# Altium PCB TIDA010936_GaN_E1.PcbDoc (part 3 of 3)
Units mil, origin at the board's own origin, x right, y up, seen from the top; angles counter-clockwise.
Board outline 2755.91 x 2708.83 mil, 4 copper layers (Top Layer, POWER, GND, Bottom Layer), stack 64.224 mil thick; 223 components, 99 nets, 571 pads, 439 vias.
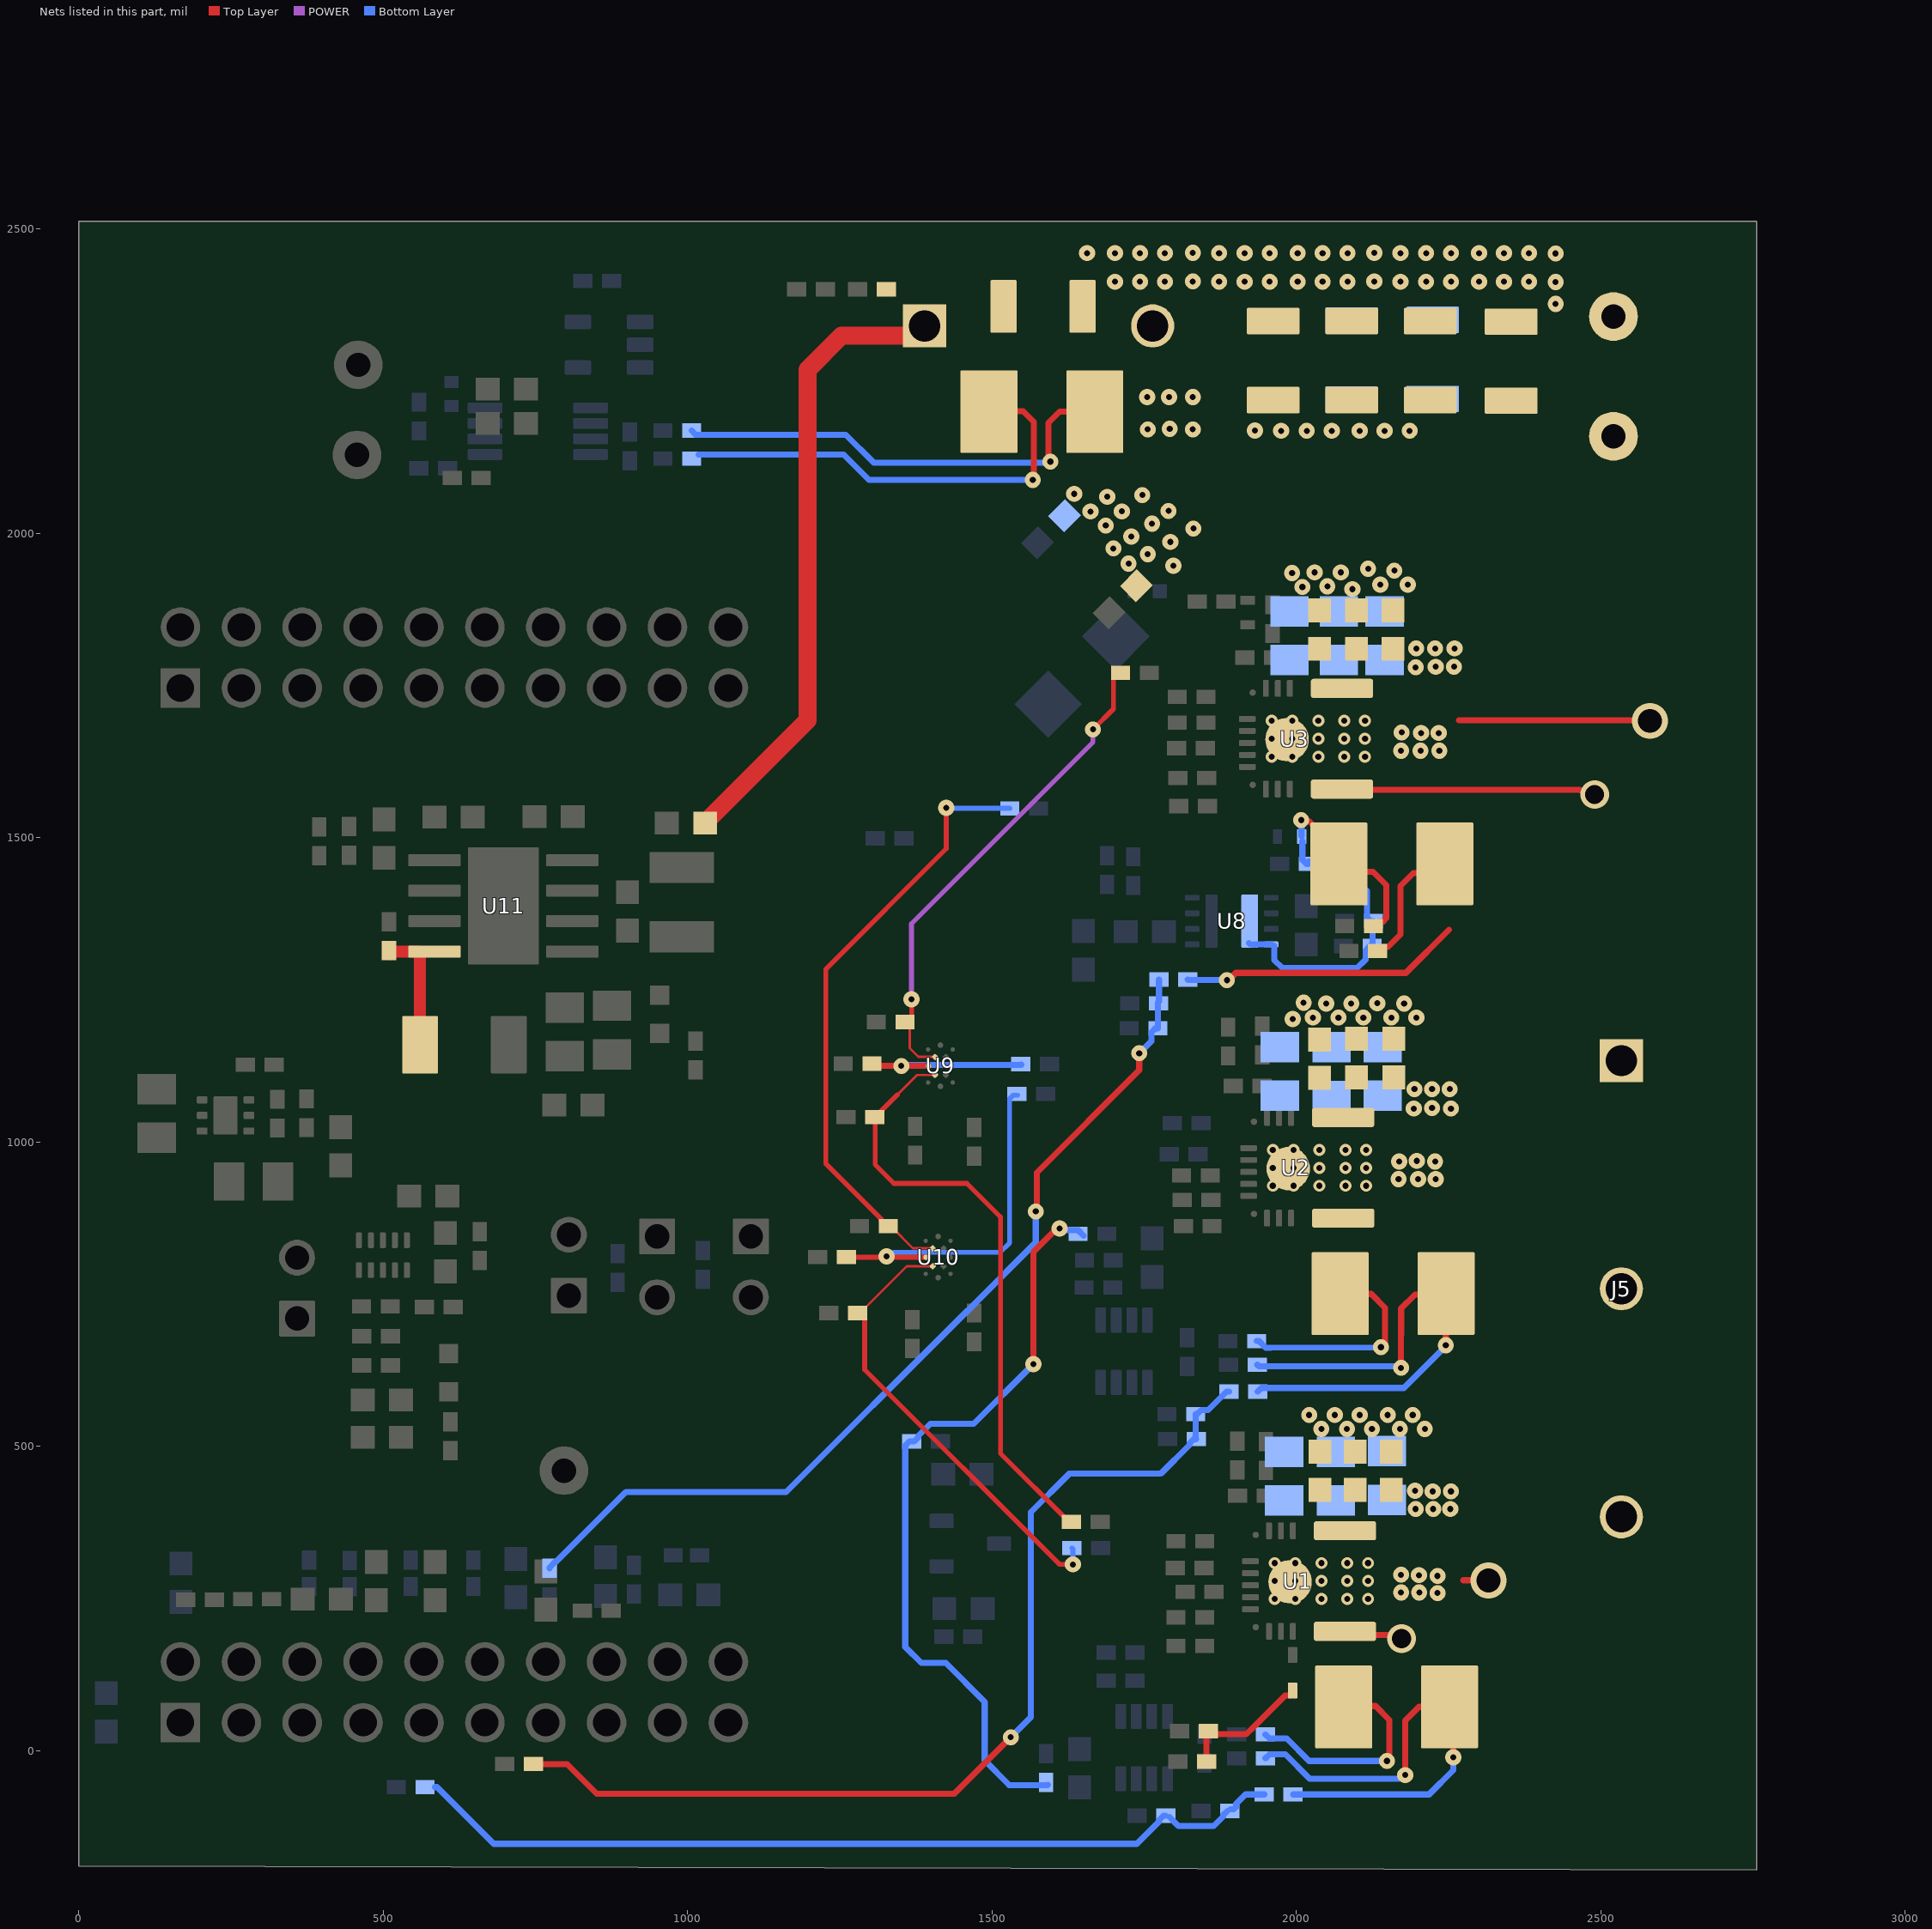
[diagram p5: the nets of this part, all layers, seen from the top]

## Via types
v1: diameter 26.38, hole 10, Top Layer to Bottom Layer, 324 vias
v2: diameter 19.68, hole 10, Top Layer to Bottom Layer, tented both sides, 45 vias
v3: diameter 24, hole 10, Top Layer to Bottom Layer, tented both sides, 39 vias
v4: diameter 47.24, hole 31.5, Top Layer to Bottom Layer, 10 vias
v5: diameter 24.8, hole 12.99, Top Layer to Bottom Layer, tented both sides, 6 vias
v6: diameter 59.06, hole 39.37, Top Layer to Bottom Layer, 5 vias
v7: diameter 24, hole 8, Top Layer to Bottom Layer, tented both sides, 4 vias
v8: diameter 29.68, hole 17.87, Top Layer to Bottom Layer, 3 vias
v9: diameter 141.73, hole 141.73, Top Layer to Bottom Layer, 2 vias
v10: diameter 31.5, hole 15.75, Top Layer to Bottom Layer, 1 vias

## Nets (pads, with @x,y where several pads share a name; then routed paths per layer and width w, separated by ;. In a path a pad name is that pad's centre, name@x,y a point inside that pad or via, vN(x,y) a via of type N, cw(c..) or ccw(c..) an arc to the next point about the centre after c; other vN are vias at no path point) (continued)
PGND: C1.2 C2.2 C3.1 C4.2 C5.2 C6.2 C7.2 C8.2 C9.2 C10.2 C13.2 C15.2 C16.2 C17.2 C18.2 C19.2 C21.2 C22.2 C23.2 C32.2 C33.2 C34.2 C36.2 C38.2 C39.2 J6.2 NT1.1 NT2.1 R2.1 R79.1 TP5.1 U1.6 U2.6 U3.6 | length 352.5
  Top Layer w10: 2267.31,1693 2580,1693 v6(2581,1692) ; 2274,280 2311,280 v6@2312,281
  other v1: 2232,259 2172,260 2202,260 2232,287 2201.44,288.25 2172,289 2041.17,528.52 2083.17,528.52 2124.17,528.52 2170.17,528.52 2211.17,528.52 2021.17,551.52 2063.17,551.52 2104.17,551.52 2150.17,551.52 2191.17,551.52 2168,939 2200,939 2229,939 2169,968 2228,968 2198,969 1994,1202 2027.17,1204.52 2069.17,1204.52 2110.17,1204.52 2156.17,1204.52 2197.17,1204.52 2049.17,1227.52 2090.17,1227.52 2133,1228 2177.17,1227.52 2012,1229 2172,1643 2204,1643 2235,1643 2205,1672 2234,1672 2173,1673 2092.17,1908.52 2010,1912 2051,1913 2138,1916 2183,1916 1993,1935 2030,1936 2073,1936 2161,1939 2118,1942 1798,1947 1724.44,1950.32 1756,1966 1699.44,1975.32 1793,1986 1729,1995 1831,2008 1687,2013 1763,2016 1662,2036 1713.44,2036.32 1790,2037 1689.44,2060.32 1747,2063 1635,2065 2426,2377 2426,2413 1702.17,2413.52 1743.17,2413.52 1784.17,2413.52 1830,2414 1873.17,2413.52 1915.17,2413.52 1956.17,2413.52 2002.17,2413.52 2043.17,2413.52 2084.17,2413.52 2128,2414 2171.17,2413.52 2213.17,2413.52 2254.17,2413.52 2300.17,2413.52 2341.17,2413.52 2382.17,2413.52 2426,2460 1656.17,2460.52 1702.17,2460.52 1743.17,2460.52 1784.17,2460.52 1830,2461 1873.17,2460.52 1915.17,2460.52 1956.17,2460.52 2002.17,2460.52 2043.17,2460.52 2084.17,2460.52 2128,2461 2171.17,2460.52 2213.17,2460.52 2254.17,2460.52 2300.17,2460.52 2341.17,2460.52 2382.17,2460.52
  other v2: 1964.34,249.12 1998.59,249.12 2041.11,249.12 2083.63,249.12 2117.88,249.12 1964.34,278.65 1998.59,278.65 2041.11,278.65 2083.63,278.65 2117.88,278.65 1964.34,308.18 1998.59,308.18 2041.11,308.18 2083.63,308.18 2117.88,308.18 1961.34,928.12 1995.59,928.12 2038.11,928.12 2080.63,928.12 2114.88,928.12 1961.34,957.65 1995.59,957.65 2038.11,957.65 2080.63,957.65 2114.88,957.65 1961.34,987.18 1995.59,987.18 2038.11,987.18 2080.63,987.18 2114.88,987.18 1959.34,1633.12 1993.59,1633.12 2036.11,1633.12 2078.63,1633.12 2112.88,1633.12 1959.34,1662.65 1993.59,1662.65 2036.11,1662.65 2078.63,1662.65 2112.88,1662.65 1959.34,1692.18 1993.59,1692.18 2036.11,1692.18 2078.63,1692.18 2112.88,1692.18
  other v6: 2315.56,279.68
Ph-A: R18.1 R24.2 U1.5 | length 500.7
  Top Layer w10: R18.1@2040.76,73.4 2130,73.4 2152.76,50.64 v1@2152.76,-13.11 ; U1.5@2080.01,195.97 2085.99,189.99 2167.01,189.99 v4(2173,184)
  Bottom Layer w10: R24.2@1949.35,26.62 1955.98,20 1984,20 2020.99,-16.99 v1(2148.88,-16.99)
Ph-B: R26.1 R30.2 U2.5 | length 395
  Top Layer w10: R26.1@2033.89,750.46 2123.12,750.46 2145.88,727.7 v1@2145.88,663.95
  Bottom Layer w10: R30.2@1934.78,672.97 1938.72,672.97 1949.69,662 1955,662 ; 1958,662 2138.49,662.49 v1(2139,663) ; v1@2139.01,661.97 v1@2142,662 ; v1@2141.56,663.16 v1@2142.14,663.74
Ph-C: C56.2 C57.2 C65.2 C66.2 R39.1 R41.2 U3.5 U8.4 | length 1224.2
  Top Layer w10: v1(2008,1529) 2009.85,1527.15 2020.91,1527.15 2069.99,1478.06 R39.1@2069.99,1457 ; R39.1@2068.99,1444 2126,1444 ; U3.5@2075.01,1579.97 2076.49,1578.49 2465.44,1578.49 2465.8,1578.13 2482.87,1578.13 v4(2490,1571) ; R41.2@2122,1349 2134.81,1361.81 2142.14,1361.81 2148,1367.67 2148,1422 2128,1442
  Bottom Layer w10: U8.4@1922,1327 U8.4@1924.31,1324.69 ; U8.4@1929,1324 U8.4@1929.61,1324.61 ; U8.4@1933,1324 1933.61,1324.61 U8.4@1958.96,1324.61 ; U8.4@1964,1323 1964,1299 1977,1286 2100,1286 2113.87,1299.87 2113.87,1315.19 2120.68,1322 C65.2@2124.62,1322 2125,1322.38 C66.2@2125,1362 ; v1@2008,1527 2008.5,1526.5 2008.5,1502.5 C57.2@2009,1502 ; v1@2009.85,1527 2009.85,1528.85 v1@2011,1530 ; C57.2@2010,1494 2010,1463.81 2016.81,1457 C56.2@2019.62,1457 ; C56.2@2019.62,1461 2067,1461 2115,1413 ; 2115.87,1413 2115.87,1369.81 2122.68,1363 C66.2@2126.62,1363
PWM_AH: R9.2 R58.2 U9.10 | length 994.7
  Top Layer w4: 1345,1079 1345.82,1079 1376.83,1110.02 1406.27,1110.02 U9.10@1406.68,1110.43
  Top Layer w8: R58.2@1308,1044 1308,963 1339,932 1459,932 1514,877 1514,488.44 1626.44,376 R9.2@1630.38,376 ; R58.2@1312.05,1045.23 1344.49,1077.67
PWM_AL: R11.2 R61.2 U10.10 | length 743
  Top Layer w4: R61.2@1288.22,724 1360.25,796.02 1399.38,796.02 1399.79,795.61 1402.53,795.61 U10.10@1402.95,796.02
  Top Layer w8: R61.2@1289,721 1291.01,718.99 1291.01,625.99 1611,306 v1(1633,306)
  Bottom Layer w8: R11.2@1631.38,333 1633,331.38 v1(1633,306)
PWM_BH: R8.2 R59.2 U9.9 | length 292.8
  Top Layer w10: R59.2@1302.89,1128.63 1306.52,1125 v1(1351.09,1125) U9.9@1395.66,1125
  Bottom Layer w10: v1@1351,1126 v1@1351.55,1125.45 ; v1(1351.09,1125) 1352.59,1126.5 1547.5,1126.5 R8.2@1548,1127
PWM_BL: R10.2 R62.2 U10.9 | length 594.9
  Top Layer w8: R62.2@1260.87,810.98 1261.07,810.79 1391.73,810.79 U10.9@1391.93,810.59
  Bottom Layer w8: v1(1326.92,812.19) 1331.89,812.19 1338.7,819 1514,819 1529.01,834.01 1529.01,1071.19 1534.82,1077 R10.2@1542,1077
PWM_CH: R16.2 R60.2 U9.8 | length 819.1
  Top Layer w4: R60.2@1365,1192 1365,1154 1379.1,1139.9 U9.8@1406.36,1139.9
  Top Layer w8: R60.2@1356.6,1196.32 R60.2@1362.96,1189.96 ; R60.2@1357.33,1197.05 1360.19,1197.05 1368,1204.86 v1@1368,1233 ; U9.8@1406.36,1139.9 U9.8@1406.69,1139.57 ; v1(1666,1678) 1699.63,1711.63 1699.63,1763.19 1706.44,1770 R16.2@1713,1770
  POWER w8: v1(1367.77,1234.44) 1367.77,1358.77 1666,1657 v1(1666,1678)
PWM_CL: R17.2 R63.2 U10.8 | length 1001.6
  Top Layer w4: R63.2@1334,859 1336.56,859 1369.98,825.57 1402.53,825.57 U10.8@1402.95,825.16
  Top Layer w8: R63.2@1329.62,862 1325.68,862 1317.87,869.81 1317.87,873.75 1227,964.62 1227,1284 1425,1482 v1(1425,1549)
  Bottom Layer w8: v1(1425,1549) 1425.5,1548.5 1528.88,1548.5 R17.2@1529.38,1548
SW: C78.1 L4.1 U11.8 | length 196.5
  Top Layer w20: C78.1@511.49,1309 515.49,1313 U11.8@558.49,1313 ; U11.8@558.49,1309 560.49,1307 L4.1@560.49,1162
Temp: R12.1 R57.1 RT1.2 | length 204.5
  Top Layer w10: R57.1@1852.62,-18 1852.62,29.62 R12.1@1854,31 ; 1872,27 1918,27 1931,40 1981.68,90.68 1991.13,90.68 1994,93.55 RT1.2@1994,98.87
V_BUS: C2.1 C3.2 C4.1 C5.1 C6.1 C7.1 C8.1 C9.1 C10.1 C13.1 C15.1 C16.1 C17.1 C18.1 C19.1 C21.1 C22.1 C23.1 C32.1 C33.1 C34.1 C36.1 C38.1 C39.1 R1.2 R35.2 TP1.1 U1.7 U2.7 U3.7 | length 760.9
  Top Layer w10: v1(1596,2118) 1593,2121 1593,2182 1611,2200 R1.2@1669.01,2200
  Bottom Layer w10: R35.2@1006.62,2169 1013.43,2162.19 1023.04,2162.19 1023.23,2162 1260,2162 1306,2116 1594,2116 v1(1596,2118)
  other v1: 2196,397 2225,397 2253,397 2224,426 2254,426 2195,427 2193,1055 2254,1055 2223,1056 2194,1087 2223,1087 2252,1087 2196,1780 2229,1781 2259,1781 2197,1811 2228,1811 2260,1811 1932,2169 1975.17,2168.52 2017.17,2168.52 2058.17,2168.52 2104.17,2168.52 2145.17,2168.52 2186.17,2168.52 1756,2171 1830,2171 1792,2172 1755,2224 1791,2224 1830,2224
VA: C44.1 R19.1 R21.2 R50.1 | length 1440.7
  Bottom Layer w10: 585,-60 588.56,-60 681.56,-153 1738.14,-153 1774.87,-116.27 1774.87,-113.81 1781.68,-107 C44.1@1785.62,-107 ; C44.1@1791.56,-109 1806.24,-123.68 1864.46,-123.68 1879.87,-108.27 1879.87,-105.81 R21.2@1886.68,-99 ; R21.2@1892,-96 1897.56,-96 1901.37,-92.19 1901.37,-87.26 1916.63,-72 R19.1@1947.38,-72
VA-Motor: J5.3 R18.2 R19.2 R23.2 | length 750.7
  Top Layer w10: v1(2179,-40) 2178.6,-39.6 2178.6,49.12 2201.35,71.88 R18.2@2251.76,71.88 ; R18.2@2257,15 2258,14 v1(2258,-11)
  Bottom Layer w10: R23.2@1949.35,-12.62 1955.98,-6 1982,-6 2022,-46 2168.57,-46 2174.57,-40 v1(2179,-40) ; R19.2@1994.62,-72 2218,-72 2258,-32 v1(2258,-11)
VB: C52.1 R27.1 R29.2 R51.1 | length 1658.3
  Top Layer w10: R51.1@746.62,-22 802,-22 851,-71 1438,-71 v1(1531,22)
  Bottom Layer w10: v1(1531,22) 1564,55 1564,392 1627,455 1777.14,455 1824.87,502.73 1824.87,505.19 1831.68,512 R29.2@1835.62,512 ; R29.2@1834.62,512 C52.1@1834.62,553 ; C52.1@1837,553 1843.81,559.81 1855.25,559.81 1885.44,590 R27.1@1889.38,590
VB-Motor: J5.2 R26.2 R27.2 R31.2 | length 812.1
  Top Layer w10: v1@2172,637 2172.12,726.7 2194.88,749.46 R26.2@2284.11,749.46 ; v1(2245.53,666.04) 2245.53,690.53 R26.2@2246,691
  Bottom Layer w10: R31.2@1935.9,634 1938.4,631.5 2169.5,631.5 v1(2172,629) ; R27.2@1936.62,590 1942.62,596 2177,596 v1@2244,663
VC: C63.1 R42.1 R46.2 R53.1 | length 1539.5
  Top Layer w10: v1(1572,886) 1573.57,887.57 1573.57,949.57 1742,1118 v1(1742,1146)
  Bottom Layer w10: R53.1@773.16,299.62 773.16,300.92 782.61,310.37 783.91,310.37 898.54,425 1162,425 1445,708 1476,739 1572,835 v1(1572,886) ; v1(1742,1146) 1761.87,1165.87 1761.87,1180.19 1768.68,1187 C63.1@1772.62,1187 1772.62,1229.62 1774.38,1231.38 R42.1@1774.38,1267
VC-Motor: J5.1 R39.2 R42.2 R45.2 | length 676.3
  Top Layer w10: v1(1886,1266) 1888.62,1266 1900.62,1278 2180,1278 2251,1349 ; R45.2@2133.62,1314 2140.43,1320.81 2150.81,1320.81 2171.14,1341.14 2171.14,1420.95 2192.14,1441.95 R39.2@2246.01,1441.95
  Bottom Layer w10: R42.2@1821.62,1267 1822.12,1266.5 1885.5,1266.5 v1(1886,1266)
VDC: C1.1 J6.1 R1.1 R20.2 R36.2 R64.2 | length 1786.8
  Top Layer w10: R20.2@1324,2401 R20.2@1326.62,2401 ; R20.2@1329,2404 R20.2@1337.37,2395.63 ; R1.1@1494.99,2201 1551,2201 1569,2183 1569,2090 v1(1567,2088)
  Top Layer w30: R64.2@1034,1530 1197,1693 1197,2269 1253,2325 1373.2,2325 J6.1@1389.2,2341
  Bottom Layer w10: R36.2@1017.81,2129.81 1256.19,2129.81 1298,2088 v1(1567,2088)
VREF: R25.1 R28.2 R32.2 | length 1270.4
  Top Layer w10: v1(1568,635) 1568,819.43 1606.57,858 v1(1611,858)
  Bottom Layer w10: 1528,-57 1591,-57 R25.1@1592,-56 ; 1528,-56 1488,-16 1488,80 1424,144 1384,144 1357.63,170.37 1357.63,501.19 1364.44,508 R28.2@1368.38,508 1372.32,508 1379.13,514.81 1379.13,517.27 1387,525.14 1398.86,537 1470,537 1567,634 v1@1567,635 ; v1(1611,858) 1614.13,854.87 1641.91,854.87 R32.2@1650.63,846.14
pads on no net: J2.3 J2.5 J2.7 J2.9 J2.11 J2.13 J2.15 J2.17 J2.19 J2.20 J3.4 J3.6 J3.8 J3.12 J3.13 J3.14 J3.15 J3.16 J3.17 J3.18 J3.19 J3.20 LBL1.0 R14.2 U1.1 U1.2 U1.3 U1.4 U1.8 U1.9 U1.16 U2.1 U2.2 U2.3 U2.4 U2.8 U2.9 U2.16 U3.1 U3.2 U3.3 U3.4 U3.8 U3.9 U3.16 U8.7 U9.5 U10.5 U11.6 U12.5 U12.7@241,1026 U12.7@241,1061.43 U13.4 U14.1
copper on no net: | length 1
  Top Layer w10: 666.52,1666 667.5,1666
  other v9: 1382,39.37 2529.26,1844.26

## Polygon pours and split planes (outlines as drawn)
VC-Motor on Top Layer "TOP_LAYER_VC-MOTOR_P097" (solid, remove dead copper, pour order 97): 2198,1390 2198,1389 2539,1048 2558,1048 2612.64,1102.64 2615.73,1119.34 2291,1525 2273,1525
VB-Motor on Top Layer "TOP_LAYER_VB-MOTOR_P096" (solid, remove dead copper, pour order 96): 2262,818 2589,818 2597,810 2597,689 2591,683 2263,683
GND on Top Layer "TOP_LAYER_GND_P095" (solid, remove dead copper, pour order 95): 30.14,2401.66 111,2482.53 1108,2482.53 1918,1672.53 1918,-140.47 1890,-168.47 59,-168.47 25.88,-135.35
PGND on Top Layer "TOP_LAYER_PGND_P088" (solid, remove dead copper, pour order 88): 1590,2042 1643,2095 2358,2095 2413,2040 2413,1856 1767,1856 1716,1907
VA-Motor on Top Layer "TOP_LAYER_VA-MOTOR_P086" (solid, remove dead copper, pour order 86): 2206,139 2377,139 2486,248 2486,410 2507,431 2578,431 2599,410 2599,226 2376,3 2375,4 2207,4
PGND on Top Layer "TOP_LAYER_PGND_P084" (solid, remove dead copper, pour order 84): 1960.35,1939 1992.35,1971 2233,1971 2264,1940 2264,1878 2242,1856 2006,1856 1960.35,1931.65
V_BUS on Top Layer "TOP_LAYER_V_BUS_P083" (solid, remove dead copper, pour order 83): 2017,1831 2017,1790 2023,1784 2023,1732 2343,1732 2346,1831
PGND on Top Layer "TOP_LAYER_PGND_P082" (solid, remove dead copper, pour order 82): 1983,1239.65 2010.35,1267 2251,1267 2282,1236 2282,1174 2260,1152 2018.35,1152 1983,1187.35
V_BUS on Top Layer "TOP_LAYER_V_BUS_P079" (solid, remove dead copper, pour order 79): 1997,1122 1999,1085 2005,1075 2005,1023 2325,1023 2328,1122
PGND on Top Layer "TOP_LAYER_PGND_P028" (solid, remove dead copper, pour order 28): 1960,1702 2281,1702 2281,1633 2270,1622 1970,1622 1960,1632
PGND on Top Layer "TOP_LAYER_PGND_P029" (solid, remove dead copper, pour order 29): 1957,995 2291.99,993.94 2290,919 1967,918 1957,928
PGND on Top Layer "TOP_LAYER_PGND_P052" (solid, remove dead copper, pour order 52): 1727,2316 1727,2433 1775,2481 2675,2481 2707,2449 2707,2337 2674,2304 1739,2304
PGND on Top Layer "TOP_LAYER_PGND_P061" (solid, remove dead copper, pour order 61): 1819,2305 1819,2482 1649,2482 1612,2445 1612,2334 1641,2305
VDC on Top Layer "TOP_LAYER_VDC_P060" (solid, remove dead copper, pour order 60): 1316,2431.4 1316,2136.5 1337,2115.5 1527,2115.5 1542,2130.5 1542,2423.5 1513,2452.5 1331.07,2452.5
V_BUS on Top Layer "TOP_LAYER_V_BUS_P059" (solid, remove dead copper, pour order 59): 2400,2244 2693,2244 2706,2231 2706,2123 2680,2097 2427,2097 2386,2138
V_BUS on Top Layer "TOP_LAYER_V_BUS_P051" (solid, remove dead copper, pour order 51): 1705.5,2244 1707.5,2242 2401.5,2242 2423.5,2220 2423.5,2152 2402.5,2134 2401.25,2129.01 1704.49,2133.01
GND on Top Layer "TOP_LAYER_GND_P043" (solid, remove dead copper, pour order 43): 1847,1610 1887,1610 1900,1597 1900,1471 1891,1462 1859,1462 1847,1474
5V on Top Layer "TOP_LAYER_5V_P038" (solid, remove dead copper, pour order 38): 981.25,1068.75 972,1078 840,1078 825,1063 825,1000 838.3,990 843,990 957,990 979,1012 979,1080
5VGAN on Top Layer "TOP_LAYER_5VGAN_P035" (solid, remove dead copper, pour order 35): 1830.14,835.14 1812,817 1792,817 1777,832 1777,955 1792,970 1822,970 1833,959
5VGAN on Top Layer "TOP_LAYER_5VGAN_P034" (solid, remove dead copper, pour order 34): 1810.97,1655.03 1826,1640 1826,1504 1781,1504 1763,1522 1763,1641 1776.13,1654.13
PGND on Top Layer "TOP_LAYER_PGND_P030" (solid, remove dead copper, pour order 30): 1959.6,318.83 2280.6,318.83 2280.6,252.6 2266.83,238.83 1969.6,238.83 1959.6,248.83
PGND on Top Layer "TOP_LAYER_PGND_P025" (solid, remove dead copper, pour order 25): 1987.65,560 2014.65,587 2305.65,587 2323.65,569 2323.65,485 2310.65,472 2022.65,472 1987.65,507
V_BUS on Top Layer "TOP_LAYER_V_BUS_P015" (solid, remove dead copper, pour order 15): 2005,444 2005,417 2025,397 2025,345 2318,346 2320.58,444
Ph-B on Top Layer "TOP_LAYER_PH-B_P003" (solid, remove dead copper, pour order 3): 2119,891.63 2119,780.37 2025,780.37 2025,891.63
Ph-A on Top Layer "TOP_LAYER_PH-A_P008" (solid, remove dead copper, pour order 8): 2028,211 2027,112 2027,5 2123,5 2124,4 2124,211 2037,211
Ph-C on Top Layer "TOP_LAYER_PH-C_P014" (solid, remove dead copper, pour order 14): 2118,1586.26 2118,1475 2023.75,1475 2023.75,1586.26
GND on Bottom Layer "BOTTOM_LAYER_GND_P093" (solid, remove dead copper, pour order 93): 27.91,2445.61 76.74,2494.44 1089.74,2494.44 1896.7,1687.48 1896.7,7.46 1723.7,-165.54 153.73,-165.54 23.74,-35.55
PGND on Bottom Layer "BOTTOM_LAYER_PGND_P087" (solid, remove dead copper, pour order 87): 1934.25,2487 2436,2487 2436,-146.97 2402.93,-180.03 2397.93,-175.03 1987.93,-175.03 1929.93,-117.03
V_BUS on Bottom Layer "BOTTOM_LAYER_V_BUS_P085" (solid, remove dead copper, pour order 85): 1954,1826.74 1957,1829.75 2294.49,1829.75 2291.39,1758.74 1965,1758.74 1954,1769.74 1954,1792.65
V_BUS on Bottom Layer "BOTTOM_LAYER_V_BUS_P081" (solid, remove dead copper, pour order 81): 1942,1089 1945,1092 2282.49,1092 2279.39,1021 1953,1021 1942,1032 1942,1054.91
PGND on Bottom Layer "BOTTOM_LAYER_PGND_P077" (solid, remove dead copper, pour order 77): 2429.43,2488 2672,2488 2709,2451 2709,2315 2685,2291 2427,2291
V_BUS on Bottom Layer "BOTTOM_LAYER_V_BUS_P072" (solid, remove dead copper, pour order 72): 1944.8,434 1947.81,437 2285.29,437 2282.2,366 1955.8,366 1944.8,377 1944.8,399.91
V_BUS on Bottom Layer "BOTTOM_LAYER_V_BUS_P069" (solid, remove dead copper, pour order 69): 2045.5,2244 2039,2237.5 2039,2159.5 2048.5,2150 2259.5,2150 2274.5,2165 2274.5,2237 2266.5,2245
PGND on Bottom Layer "BOTTOM_LAYER_PGND_P064" (solid, remove dead copper, pour order 64): 1937.25,2488 1222,2488 1225,2421 1890.28,1722 1937.25,1722
GND on POWER "POWER_GND_P089" (solid, remove dead copper, pour order 89): 60.39,2362.82 162.99,2465.42 1137.32,2465.42 1843.16,1759.59 1843.16,-222.41 120.16,-222.41 56.16,-158.41
5VGAN on POWER "POWER_5VGAN_P033" (solid, remove dead copper, pour order 33): 1789.5,1734.75 1774,1719.25 1774,-180.75 1846.52,-180.75 1855,-150 1855,229.25 1855,1719.25 1838.23,1736.02
PGND on POWER "POWER_PGND_P078" (solid, remove dead copper, pour order 78): 2429.42,2487 2646,2487 2709,2424 2709,2332 2668,2291 2427,2291
PGND on POWER "POWER_PGND_P065" (solid, remove dead copper, pour order 65): 1950.63,2492.51 1331,2491.51 1339,2312 1896.58,1720 1938,1720
PGND on POWER "POWER_PGND_P046" (solid, remove dead copper, pour order 46): 1931,2474 1931,2492 2430.88,2487.87 2435,2478.8 2435,2309 2435,-146 2434,-146 2405,-175 2401,-171 1943.67,-171
GND on GND "GND_GND_P091" (solid, remove dead copper, pour order 91): 50.83,2450.83 97,2497 1115,2497 1923,1689 1923,-117 1875,-165 131,-165 46.58,-80.58
V_BUS on GND "GND_V_BUS_P057" (solid, remove dead copper, pour order 57): 1721.5,2265 1722.5,2266 1954.44,2266 1973.5,2242.65 1973.5,2139 1971.5,2139 1953.5,2121 1636.5,2121 1606.5,2151 1606.5,2246 1625.5,2265
V_BUS on GND "GND_V_BUS_P055" (solid, remove dead copper, pour order 55): 1940,2326 1959,2345 2415.29,2345 2432,2324.28 2432,-128 2400,-160 1980,-160 1935.95,-115.95
V_BUS on GND "GND_V_BUS_P074" (solid, remove dead copper, pour order 74): 2429,2242.1 2697.1,2242.1 2710.1,2229.1 2710.1,2076.1 2695,2061 2429,2061 2429,2082

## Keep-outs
Keep-Out Layer:
  text ".Layer_Name" at 577,-858.49 h60

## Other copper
Top Layer:
  pour cut-out: 1398,775 1506,775 1508,773 1507,772 1507,667 1418,667 1397,688
  pour cut-out: 2346.33,1728.15 2345.33,1729.15 2345.33,1743.15 2330.33,1728.15
  pour cut-out: 2331.98,1020.41 2330.98,1021.41 2330.98,1035.41 2315.98,1020.41
  pour cut-out: 2328,340 2328,361 2305.17,338.17
  pour cut-out: 200,225 325,225 325,75 200,75
  pour cut-out: 1426,1152 1429,1155 1429,1162 1441,1162 1444,1159
  pour cut-out: 1241.98,782 1324,782 1324,730 1266,672 1247,673
  pour cut-out: 2296,915 2295,916 2295,930 2280,915
  pour cut-out: 1211.93,2340.07 1143.5,2408.5 1150,2415 1218,2347
  pour cut-out: 403,310 404,309 452,309 452,186 448,182 398,182
  region net GND: 550.51,494 511.51,494 508.51,497 509.51,498 509.51,608 496.51,621 496.51,644 506.51,654 535.51,654 598.51,717 598.51,749 574.51,773 518.51,773 514.51,777 514.51,802 518.51,806 631.51,806 646.51,821 674.51,821 682.51,813 682.51,666 652.51,636 592.51,636 563.51,607 563.51,507
  region net NetC87_1: 485.51,497 479.51,491 431.51,491 423.51,499 423.51,836 438.51,851 464.51,851 464.51,819.27 484.51,802 484.51,497
  region net NetC87_1: 427.51,760 414.51,773 328.51,773 318.51,783 318.51,838 331.51,851 441.51,851 441.51,761 438.51,758
  region net GND: 285,1146 289,1142 289,1065 287,1063 264,1063 261,1060 261,978 273,966 273,903 269,899 223,899 221,901 221,1010 221,1136 231,1146 283,1146
  region net GND: 204,1103 228,1079 228,1098 232,1102
  region net GND: 161,1063 161,1072 187,1098 228,1098 232,1102 232,1146 128,1146 93,1111 93,1065 97,1061 159,1061
  region net GND: 1036.49,1370 1044.49,1362 1044.49,1261.49 1037,1254 926,1254 914,1242 914,1202 905,1193 767.49,1193 759.49,1201 759.49,1237 707.49,1289 641.49,1289 639.49,1291 639.49,1500 626.49,1513 626.49,1615 630.49,1619 739.49,1619 770.49,1588 770.49,1504 755.49,1489 755.49,1337 768.49,1324 858.49,1324 880.49,1346 880.49,1365 885.49,1370
  pour cut-out: 2285.5,325.5 2264.5,325.5 2264.5,323.5 2287.5,300.5
  pour cut-out: 2282,1702 2281,1702 2268,1702 2281.12,1688.88
  text ".Layer_Name" at 577,-858.49 h60
POWER:
  pour cut-out: 1345,852.5 1369,840.5 1369,787.5 1340,758.5 1338,760.5 1290,760.5 1290,849.5 1301,860.5
  pour cut-out: 1425.72,825.45 1499.97,809.03 1503,773 1407.94,717 1352,717 1352,794 1363,805
  pour cut-out: 1376,1184 1400,1172 1400,1119 1371,1090 1369,1092 1321,1092 1321,1155 1354,1188
GND:
  pour cut-out: 1333.99,823 1507,823 1532.5,797.5 1507,772 1462,716 1405.7,653.3 1332.88,726.12
  pour cut-out: 1343.94,852.42 1367.94,840.42 1367.94,787.42 1338.94,758.42 1336.94,760.42 1288.94,760.42 1288.94,823.42 1321.94,856.42
  pour cut-out: 1385,1185 1395,1175 1395,1108 1372,1085 1366,1091 1310,1091 1310,1141 1354,1185
Bottom Layer:
  pour cut-out: 2285,362 2282,365 2278,365 2278,366 2284,372
  pour cut-out: 1309,855 1308,854 1308,716 1326,698 1436,698 1468,730 1339,859 1330,859
  pour cut-out: 1746,-27 1745,-28 1745,-72 1759,-72 1762,-69 1762,-27
  text ".Layer_Name" at 577,-858.49 h60

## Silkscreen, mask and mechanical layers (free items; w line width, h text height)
Top Overlay:
  lines w10: 1207.57,-174 2743,-174 2743,2109.46 1207.57,2109.46 1207.57,-174
  text "'.PRJ_Number'.PCB_Rev" at 100,2350 h108.27
  text "48V" at 1316,2248.93 h80
  text "GND" at 1733,2248.89 h80
  text "Heatsink" at 2484,2036 h30
  text "VC" at 2639.11,1085 h80 r90
  text "VB" at 2640,715 h80 r90
  text "GND" at 857.18,422.51 h60
  text "VA" at 2640,335 h80 r90
  text ".Layer_Name" at 577,-858.49 h60
Bottom Overlay:
  text ".Layer_Name" at 577,-858.49 h60
Top Paste:
  text ".Layer_Name" at 577,-858.49 h60
Bottom Paste:
  text ".Layer_Name" at 577,-858.49 h60
Top Solder:
  text ".Layer_Name" at 577,-858.49 h60
  text ".Layer_Name" at 577,-858.49 h60
Bottom Solder:
  region: 1949.5,312.07 1955.5,318.07 2269.5,318.07 2277.5,310.07 2277.5,248.93 2272.5,241.07 1955.5,241.07 1949.5,247.07
  region: 1945,1696 1951,1702 2285,1702 2292,1695 2292,1628 2286,1625 2283,1625 1951,1625 1945,1631
  region: 1941,992 1947,998 2281,998 2288,991 2288,924 2282,921 2279,921 1947,921 1941,927
  text ".Layer_Name" at 577,-858.49 h60
Drill Guide:
  text ".Layer_Name" at 577,-858.49 h60
M1 Board Outline:
  the board outline again, w10
  text ".Layer_Name" at 577,-858.49 h60
M2 Board Dimensions:
  rectangle: 0,-275 125,-150
  rectangle: 125,-400 500,-275
  lines w7: 0,-275 1000,-275 ; 125,-400 125,-150 ; 250,-400 250,-150 ; 500,-400 500,-150 ; 750,-400 750,-150 ; 0,-400 1000,-400 1000,-150 0,-150 0,-400
  text ".Layer_Name" at 577,-858.49 h60
M3 3D STEP Top:
  text ".Layer_Name" at 577,-858.49 h60
M4 3D STEP Bottom:
  text ".Layer_Name" at 577,-858.49 h60
M5 Assembly Top:
  lines w10: -292,-930.17 6308,-930.17 ; -292,-726.83 6310,-726.83 ; -292,-523.5 -292,-1133.5 3713,-1133.5 6310,-1133.5 6310,-523.5 -291.5,-523.5 -291.5,-1133.5 1284,-1133.5 ; 2173,-1133.5 2173,-523.5 ; 3440,-726.83 3440,-523.5 ; 4280,-726.83 4280,-523.5 ; 4902,-1140 4902,-937.17
  text "COMPONENTS MARKED 'DNP' SHOULD NOT BE POPULATED." at 1153,-355 h60
  text "ASSEMBLY VARIANT:" at 1153,-434 h60
  text ".VariantName" at 2189,-434 h60
  text "PCB VIEWED FROM TOP SIDE" at -228.5,-655.67 h60
  text "BOARD #:" at 2248,-655.67 h60
  text ".PRJ_Number" at 2793.5,-655.67 h60
  text "REV:" at 3638,-655.67 h60
  text ".PCB_Rev" at 3929.5,-655.67 h60
  text "SVN REV:" at 4476,-655.67 h60
  text ".VersionControl_RevNumber" at 4982,-655.67 h60
  text "TID #:" at 2248,-859 h60
  text ".TID" at 2793.5,-859 h60
  text "PLOT NAME =" at -228.5,-1064.34 h60
  text ".plot_File_Name" at 577,-1064.34 h60
  text "GENERATED    :" at 2250,-1064.34 h60
  text ".Print_Date" at 3119.5,-1064.34 h60
  text ".Print_Time" at 3848.5,-1064.34 h60
  text "TEXAS INSTRUMENTS" at 5113,-1064.34 h60
M6 Assembly Bottom:
  lines w10: -292.5,-727.33 6309.5,-727.33 ; -290.5,-930.67 6309.5,-930.67 ; 1115.5,-1140.5 1115.5,-937.67 ; 1737.5,-727.33 1737.5,-524 ; 2577.5,-727.33 2577.5,-524 ; 3844.5,-1134 3844.5,-524 ; 4733.5,-1134 6309,-1134 6309,-524 -292.5,-524 -292.5,-1134 2304.5,-1134 6309.5,-1134 6309.5,-524
  text "COMPONENTS MARKED 'DNP' SHOULD NOT BE POPULATED." at 6102,-318 h60
  text ".VariantName" at 5058,-434 h60
  text "ASSEMBLY VARIANT:" at 6097,-434 h60
  text ".VersionControl_RevNumber" at 1035.5,-656.17 h60
  text "SVN REV:" at 1541.5,-656.17 h60
  text ".PCB_Rev" at 2088,-656.17 h60
  text "REV:" at 2379.5,-656.17 h60
  text ".PRJ_Number" at 3224,-656.17 h60
  text "BOARD #:" at 3769.5,-656.17 h60
  text "PCB VIEWED FROM BOTTOM SIDE" at 6246,-656.17 h60
  text ".TID" at 3224,-859.5 h60
  text "TID #:" at 3769.5,-859.5 h60
  text "TEXAS INSTRUMENTS" at 904.5,-1064.84 h60
  text ".Print_Time" at 2169,-1064.84 h60
  text ".Print_Date" at 2898,-1064.84 h60
  text "GENERATED    :" at 3767.5,-1064.84 h60
  text ".plot_File_Name" at 5440.5,-1064.84 h60
  text "PLOT NAME =" at 6246,-1064.84 h60
M9 Title Sheet:
  drawing of 57 lines, arcs and shapes, not listed
  text "1" at 739.84,8036.5 h70
  text "2" at 3235.5,8036.5 h70
  text "3" at 5724.84,8036.5 h70
  text "4" at 8231.51,8036.5 h70
  text "5" at 10730.5,8036.5 h70
  text "6" at 13235.5,8036.5 h70
  text "A" at -416.5,6893.5 h70
  text "A" at 14383.5,6893.5 h70
  text "B" at -416.5,4513.5 h70
  text "B" at 14383.5,4513.5 h70
  text "C" at -416.5,2138.5 h70
  text "C" at 14383.5,2138.5 h70
  text "PROJECT TITLE:" at 11343.5,277.5 h45
  text ".PRJ_Title" at 11393.5,144.17 h70
  text "DESIGNED FOR:" at 11343.5,-23.5 h45
  text ".PRJ_Customer" at 11393.5,-163.5 h70
  text "D" at -416.5,-231.5 h70
  text "D" at 14383.5,-231.5 h70
  text "FILE NAME:" at 11343.5,-323.5 h45
  text ".PCB_File_Name_No_Path" at 11393.5,-443.5 h70
  text "Texas Instruments (TI) and/or its licensors do not warrant the accuracy or completeness of this specification" at 6374,-605.34 h45
  text "ENGINEER:" at 11343.5,-613.5 h45
  text "LAYOUT BY:" at 12848.5,-613.5 h45
  text "or any information contained therein. TI and/or its licensors do not warrant that this design will meet" at 6329.01,-718 h45
  text ".PRJ_Engineer" at 11393.5,-768.49 h70
  text ".PCB_Layout" at 12899,-768.49 h70
  text "the specifications, will be suitable for your application or fit for any particular purpose, or will operate in" at 6329.01,-830.67 h45
  text ".Layer_Name" at 577,-858.49 h60
  text "ALTIUM DESIGNER VERSION:" at 12848.5,-923.5 h45
  text "an implementation. TI and/or its licensors do not warrant that the design is production worthy. You should" at 6329.01,-943.33 h45
  text "completely validate and test your design implementation to confirm the system functionality for your application." at 6374,-1056 h45
  text ".print_Scale" at 11393.5,-1056.83 h70
  text ".Application_BuildNumber" at 12899,-1056.83 h70
  text "1" at 739.84,-1263.5 h70
  text "2" at 3235.5,-1263.5 h70
  text "3" at 5724.84,-1263.5 h70
  text "4" at 8231.51,-1263.5 h70
  text "5" at 10730.5,-1263.5 h70
  text "6" at 13235.5,-1263.5 h70
M10 Fab Notes:
  drawing of 189 lines, arcs and shapes, not listed
  text "DESIGN INFORMATION" at 12382.02,6356.17 h60
  text "MIN. TRACK WIDTH:" at 11737.46,6224.05 h60
  text "8" at 12833.7,6224.05 h60
  text "MIL" at 12988.46,6224.05 h60
  text "7.874" at 12667.32,6102.36 h60
  text "MIN. CLEARANCE:" at 11737.46,6099.92 h60
  text "MIL" at 12988.46,6099.92 h60
  text "MIN. VIA PAD SIZE:" at 11737.46,5975.8 h60
  text "19" at 12800,5976 h60
  text "MIL" at 12988.46,5975.8 h60
  text "0.05mm (2MIL)" at 12432.46,5845.9 h60
  text "MINIMUM ANNULAR RING" at 11408.23,5837.67 h60
  text "EXTERNAL" at 13140.46,5837.67 h60
  text "PER" at 11608.23,5727.55 h60
  text "IPC-D-275 CLASS 2 LEVEL C" at 11828.23,5727.54 h60
  text "MIL, HOLES" at 13316.46,5627.07 h60
  text "+/-" at 12924,5618.48 h60
  text "+/-" at 13778,5618.48 h60
  text "REGISTRATION TOLERANCES:" at 11408.23,5617.42 h60
  text "METAL" at 12608,5617.42 h60
  text "5" at 13184.2,5617.42 h60
  text "3" at 14017.2,5617.42 h60
  text "MIL" at 14133.46,5617.42 h60
  text "HOLE SIZE TOLERANCE (UNLESS OTHERWISE SPECIFIED):" at 11408.23,5519.1 h60
  text "+/-" at 13778,5516.23 h60
  text "3" at 14017.2,5515.17 h60
  text "MIL" at 14133.46,5515.17 h60
  text "MATERIAL:" at 11333.46,5377.52 h60
  text "FR-4 High Tg" at 12319.9,5249 h60
  text "X" at 12175.46,5241.01 h60
  text "FR-4" at 11754.46,5236.49 h60
  text "OTHER" at 13242.46,5236.49 h60
  text "65 MIL (1.65mm) +/-10%" at 12074.56,5093.46 h60
  text "X" at 11954.46,5091.01 h60
  text "THICKNESS:" at 11408.23,5085.24 h60
  text "OTHER" at 13359.46,5085.24 h60
  text "TOLERANCE:" at 11408.23,4946.92 h60
  text "X" at 12256.46,4946.92 h60
  text "ANSI IPC-6012 TYPE 3 CLASS 2" at 12434.48,4946.92 h60
  text "OTHER +/-" at 12434.46,4802.73 h60
  text "BOW & TWIST:" at 11408.23,4657.54 h60
  text "X" at 12256.46,4657.54 h60
  text "ANSI IPC-6012 TYPE 3 CLASS 2" at 12434.48,4657.54 h60
  text "OTHER +/-" at 12434.46,4510.85 h60
  text "DRILLING:" at 11333.46,4380.23 h60
  text "NC_DRILL FILES" at 13094.46,4275.04 h60
  text "REFERENCE:" at 11408.23,4271.1 h60
  text "X" at 12065.46,4271.01 h60
  text "AS SHOWN" at 12243.46,4271.1 h60
  text "X" at 12966.46,4271.1 h60
  text "OTHER" at 13392.46,4128.85 h60
  text "PTH COPPER THICKNESS:" at 11407.91,4125.32 h60
  text "X" at 12547.14,4125.32 h60
  text "20-30 um" at 12675.14,4125.32 h60
  text "BOARD FINISH:" at 11333.46,3977.73 h60
  text "SILKSCREEN:" at 11488.68,3867.6 h60
  text "X" at 12446.46,3867.6 h60
  text "TOP" at 12563.46,3867.6 h60
  text "X" at 12956.46,3867.6 h60
  text "BOTTOM" at 13074.46,3867.6 h60
  text "SILKSCREEN COLOR:" at 11488.68,3712.41 h60
  text "X" at 12445.46,3712.41 h60
  text "WHITE" at 12563.46,3712.41 h60
  text "OTHER" at 13074.46,3712.41 h60
  text "X" at 12576.46,3568.96 h60
  text "GREEN" at 12694.46,3568.96 h60
  text "OTHER" at 13312.46,3568.96 h60
  text "SOLDER RESIST COLOR:" at 11488.68,3562.1 h60
  text "X" at 12576.46,3414.71 h60
  text "MATTE" at 12694.46,3414.71 h60
  text "SEMI-GLOSS" at 13312,3414.07 h60
  text "IMMERSION GOLD (ENIG)" at 12394.46,3241.94 h60
  text "ENEPIG" at 13732,3234.72 h60
  text "SURFACE FINISH:" at 11333.46,3233.72 h60
  text "X" at 12216.46,3233.72 h60
  text "IMM. TIN/SILVER OR EQUIV" at 11663,3096.4 h60
  text "OTHER" at 13094.46,3092.47 h60
  text "ARRAY/PANEL:" at 11333.46,2937.09 h60
  text "CUT AND TRIM PER M1 BOARD OUTLINE" at 12394.46,2928.87 h60
  text "N.C. ROUTE" at 12394.46,2792.9 h60
  text "X" at 13082.46,2792.9 h60
  text "V. SCORE" at 13260.46,2792.9 h60
  text "CERTIFICATION:" at 11333.46,2663.77 h60
  text "MATERIALS AND WORKMANSHIP FOR ALL PCBS" at 12058.46,2663.77 h60
  text "TO MEET OR EXCEED THE REQUIREMENTS OF:" at 12058.46,2569.71 h60
  text "X" at 11695.97,2441.08 h60
  text "ANSI IPC-A-600F CLASS ->" at 11823.96,2441.08 h60
  text "X" at 13471.97,2441.08 h60
  text "2" at 13581.96,2441.08 h60
  text "1" at 13266.96,2439.58 h60
  text "3" at 13935.96,2439.58 h60
  text "X" at 12507.97,2293.39 h60
  text "RoHS" at 12635.96,2293.39 h60
  text "OTHER" at 13280.36,2293.39 h60
  text "PER ORDER" at 13677.42,2293.39 h60
  text "ALL BOARDS MUST MEET OR EXCEED UL94-V0 REQUIREMENTS." at 11361,2139.57 h60
  text "PCB MUST BEAR THE UL94V-0 UL REGISTERED MATERIAL ID NUMBER" at 11361,2023.5 h60
  text "ADDITIONAL REQUIREMENTS:" at 11333.46,1854.08 h60
  text "MICROSECTION:" at 11408.23,1746.95 h60
  text "YES" at 12313.96,1746.95 h60
  text "REQUIRED" at 13175.46,1602.62 h60
  text "BARE BOARD ELEC. TEST:" at 11408.23,1599.76 h60
  text "NONE" at 12713.96,1599.76 h60
  text "X" at 13057.46,1599.76 h60
  text "PER ORDER" at 13767.46,1599.76 h60
  text "XX MIL VIAS REQUIRE NON-CONDUCTIVE FILL AND PLANARIZE" at 11576.38,1394.82 h59
  text "XX MIL VIAS REQUIRE CONDUCTIVE FILL AND PLANARIZE" at 11584.38,1290.84 h60
  text "OUTER XX MIL TRACES REQUIRE 50 OHM SINGLE-ENDED IMPEDANCE" at 11583.39,1127.46 h58
  text "LAYER 2 & 3 (INNER LAYERS) XX MIL WIDE, XX MIL SPACE / TRACES REQUIRE 100 OHM DIFFERENTIAL IMPEDANCE" at 11575.39,891.74 h60
  text ".Layer_Name" at 577,-858.49 h60
M11 Gerber Information:
  lines w10: -292,-930.17 6308,-930.17 ; -292,-726.83 6310,-726.83 ; -292,-523.5 -292,-1133.5 3713,-1133.5 6310,-1133.5 6310,-523.5 -291.5,-523.5 -291.5,-1133.5 1284,-1133.5 ; 2173,-1133.5 2173,-523.5 ; 3440,-726.83 3440,-523.5 ; 4280,-726.83 4280,-523.5 ; 4902,-1140 4902,-937.17
  text "ALL ARTWORK VIEWED FROM TOP SIDE" at -228.5,-655.67 h60
  text "BOARD #:" at 2248,-655.67 h60
  text ".PRJ_Number" at 2793.5,-655.67 h60
  text "REV:" at 3638,-655.67 h60
  text ".PCB_Rev" at 3929.5,-655.67 h60
  text "SVN REV:" at 4476,-655.67 h60
  text ".VersionControl_RevNumber" at 4982,-655.67 h60
  text "LAYER NAME =" at -228.5,-858.49 h60
  text "TID #:" at 2248,-859 h60
  text ".TID" at 2793.5,-859 h60
  text "PLOT NAME =" at -228.5,-1064.34 h60
  text ".plot_File_Name" at 577,-1064.34 h60
  text "GENERATED    :" at 2250,-1064.34 h60
  text ".Print_Date" at 3119.5,-1064.34 h60
  text ".Print_Time" at 3848.5,-1064.34 h60
  text "TEXAS INSTRUMENTS" at 5113,-1064.34 h60
M12 Stackup:
  drawing of 295 lines, arcs and shapes, not listed
  text "Layer" at 9821.59,7874.94 h60
  text "Name" at 10231.51,7874.94 h60
  text "Material" at 11161.25,7874.94 h60
  text "Thickness" at 12021.02,7874.94 h60
  text "Constant" at 12670.85,7874.94 h60
  text "Board Layer Stack" at 13240.71,7874.94 h60
  text "Top Overlay" at 10231.51,7754.94 h60
  text "Top Solder" at 10231.51,7634.94 h60
  text "Solder Resist" at 11161.25,7634.94 h60
  text "0.40mil" at 12021.02,7634.94 h60
  text "3.5" at 12670.85,7634.94 h60
  text "1" at 9821.59,7514.94 h60
  text "Top Layer" at 10231.51,7514.94 h60
  text "2.76mil" at 12021.02,7514.94 h60
  text "Dielectric 1" at 10231.51,7394.94 h60
  text "FR-4 High Tg" at 11161.25,7394.94 h60
  text "8.00mil" at 12021.02,7394.94 h60
  text "4.2" at 12670.85,7394.94 h60
  text "2" at 9821.59,7274.94 h60
  text "POWER" at 10231.51,7274.94 h60
  text "2.76mil" at 12021.02,7274.94 h60
  text "Dielectric 2" at 10231.51,7154.94 h60
  text "FR-4 High Tg" at 11161.25,7154.94 h60
  text "37.20mil" at 12021.02,7154.94 h60
  text "4.2" at 12670.85,7154.94 h60
  text "3" at 9821.59,7034.94 h60
  text "GND" at 10231.51,7034.94 h60
  text "2.76mil" at 12021.02,7034.94 h60
  text "Dielectric 3" at 10231.51,6914.94 h60
  text "FR-4 High Tg" at 11161.25,6914.94 h60
  text "8.00mil" at 12021.02,6914.94 h60
  text "4.2" at 12670.85,6914.94 h60
  text "4" at 9821.59,6794.94 h60
  text "Bottom Layer" at 10231.51,6794.94 h60
  text "2.76mil" at 12021.02,6794.94 h60
  text "Bottom Solder" at 10231.51,6674.94 h60
  text "Solder Resist" at 11161.25,6674.94 h60
  text "0.40mil" at 12021.02,6674.94 h60
  text "3.5" at 12670.85,6674.94 h60
  text "Bottom Overlay" at 10231.51,6554.94 h60
  text ".Layer_Name" at 577,-858.49 h60
M13 Component Bodies Top:
  text ".Layer_Name" at 577,-858.49 h60
M14 Component Bodies Bottom:
  text ".Layer_Name" at 577,-858.49 h60
M15 Courtyards Top:
  text ".Layer_Name" at 577,-858.49 h60
M16 Courtyards Bottom:
  text ".Layer_Name" at 577,-858.49 h60
Drill Drawing:
  circle w10: c-70.98,6907.2 r16.54
  circle w10: c-70.98,6907.2 r27.56
  circle w10: c-70.98,6411.09 r27.56
  lines w10: -98.54,6507.56 -70.98,6521.34 -43.41,6507.56 -57.19,6535.12 -43.41,6562.68 -70.98,6548.9 -98.54,6562.68 -84.76,6535.12 -98.54,6507.56 ; -98.54,6645.37 -84.76,6645.37 -70.98,6631.59 -57.19,6645.37 -43.41,6645.37 -57.19,6659.15 -43.41,6672.93 -57.19,6672.93 -70.98,6686.71 -84.76,6672.93 -98.54,6672.93 -84.76,6659.15 -98.54,6645.37 ; -98.54,6755.61 -43.41,6755.61 -43.41,6810.74 -98.54,6810.74 -98.54,6755.61 ; -98.54,7058.79 -43.41,7058.79 -70.98,7003.67 -98.54,7058.79 ; -98.54,7127.69 -98.54,7141.47 -84.76,7155.25 -98.54,7169.04 -98.54,7182.82 -84.76,7182.82 -70.98,7169.04 -57.19,7182.82 -43.41,7182.82 -43.41,7169.04 -57.19,7155.25 -43.41,7141.47 -43.41,7127.69 -57.19,7127.69 -70.98,7141.47 -84.76,7127.69 -98.54,7127.69 ; -98.54,7306.84 -43.41,7306.84 -70.98,7251.72 -98.54,7306.84 ; -98.54,7403.31 -70.98,7375.75 -43.41,7403.31 -70.98,7430.87 -98.54,7403.31 ; -98.54,7499.77 -70.98,7513.55 -43.41,7499.77 -57.19,7527.34 -43.41,7554.9 -70.98,7541.12 -98.54,7554.9 -84.76,7527.34 -98.54,7499.77 ; -98.54,7637.58 -84.76,7637.58 -84.76,7623.8 -57.19,7623.8 -57.19,7637.58 -43.41,7637.58 -43.41,7665.14 -57.19,7665.14 -57.19,7678.92 -84.76,7678.92 -84.76,7665.14 -98.54,7665.14 -98.54,7637.58 ; -87.51,7047.77 -54.44,7047.77 -70.98,7014.69 -87.51,7047.77 ; -87.51,7510.8 -70.98,7519.07 -54.44,7510.8 -62.71,7527.34 -54.44,7543.87 -70.98,7535.6 -87.51,7543.87 -79.24,7527.34 -87.51,7510.8
  lines w12: -148.52,6346.33 3078.28,6346.33 ; -148.52,7710.62 3078.28,7710.62 ; 188.85,6222.3 188.85,7834.65 ; 520.54,6222.3 520.54,7834.65 ; 1156.39,6222.3 1156.39,7834.65 ; 1415.19,6222.3 1415.19,7834.65 ; 1789.94,6222.3 1789.94,7834.65 ; 2512.48,6222.3 2512.48,7834.65 ; -148.52,6222.3 3078.28,6222.3 3078.28,7834.65 -148.52,7834.65 -148.52,6222.3
  text "Symbol" at -74.1,7747.83 h72
  text "Quantity" at 226.06,7747.83 h72
  text "Finished Hole Size" at 557.75,7747.83 h72
  text "Plated" at 1193.6,7747.83 h72
  text "Hole Type" at 1452.4,7747.83 h72
  text "Drill Layer Pair" at 1827.15,7747.83 h72
  text "Hole Tolerance" at 2549.69,7747.83 h72
  text "4" at 226.06,7623.8 h60
  text "8.00mil (0.203mm)" at 557.75,7623.8 h60
  text "PTH" at 1193.6,7623.8 h60
  text "Round" at 1452.4,7623.8 h60
  text "Top Layer - Bottom Layer" at 1827.15,7623.8 h60
  text "408" at 226.06,7499.77 h60
  text "10.00mil (0.254mm)" at 557.75,7499.77 h60
  text "PTH" at 1193.6,7499.77 h60
  text "Round" at 1452.4,7499.77 h60
  text "Top Layer - Bottom Layer" at 1827.15,7499.77 h60
  text "6" at 226.06,7375.75 h60
  text "12.99mil (0.330mm)" at 557.75,7375.75 h60
  text "PTH" at 1193.6,7375.75 h60
  text "Round" at 1452.4,7375.75 h60
  text "Top Layer - Bottom Layer" at 1827.15,7375.75 h60
  text "1" at 226.06,7251.72 h60
  text "15.75mil (0.400mm)" at 557.75,7251.72 h60
  text "PTH" at 1193.6,7251.72 h60
  text "Round" at 1452.4,7251.72 h60
  text "Top Layer - Bottom Layer" at 1827.15,7251.72 h60
  text "3" at 226.06,7127.69 h60
  text "17.87mil (0.454mm)" at 557.75,7127.69 h60
  text "PTH" at 1193.6,7127.69 h60
  text "Round" at 1452.4,7127.69 h60
  text "Top Layer - Bottom Layer" at 1827.15,7127.69 h60
  text "10" at 226.06,7003.67 h60
  text "31.50mil (0.800mm)" at 557.75,7003.67 h60
  text "PTH" at 1193.6,7003.67 h60
  text "Round" at 1452.4,7003.67 h60
  text "Top Layer - Bottom Layer" at 1827.15,7003.67 h60
  text "5" at 226.06,6879.64 h60
  text "39.37mil (1.000mm)" at 557.75,6879.64 h60
  text "PTH" at 1193.6,6879.64 h60
  text "Round" at 1452.4,6879.64 h60
  text "Top Layer - Bottom Layer" at 1827.15,6879.64 h60
  text "13" at 226.06,6755.61 h60
  text "40.00mil (1.016mm)" at 557.75,6755.61 h60
  text "PTH" at 1193.6,6755.61 h60
  text "Round" at 1452.4,6755.61 h60
  text "Top Layer - Bottom Layer" at 1827.15,6755.61 h60
  text "40" at 226.06,6631.59 h60
  text "45.28mil (1.150mm)" at 557.75,6631.59 h60
  text "PTH" at 1193.6,6631.59 h60
  text "Round" at 1452.4,6631.59 h60
  text "Top Layer - Bottom Layer" at 1827.15,6631.59 h60
  text "5" at 226.06,6507.56 h60
  text "51.18mil (1.300mm)" at 557.75,6507.56 h60
  text "PTH" at 1193.6,6507.56 h60
  text "Round" at 1452.4,6507.56 h60
  text "Top Layer - Bottom Layer" at 1827.15,6507.56 h60
  text "+/-3.94mil" at 2549.69,6507.56 h60
  text "2" at 226.06,6383.53 h60
  text "141.73mil (3.600mm)" at 557.75,6383.53 h60
  text "PTH" at 1193.6,6383.53 h60
  text "Round" at 1452.4,6383.53 h60
  text "Top Layer - Bottom Layer" at 1827.15,6383.53 h60
  text "497 Total" at 226.06,6259.51 h60
  text ".Layer_Name" at 577,-858.49 h60
M17 Embedded Cavity:
  text ".Layer_Name" at 577,-858.49 h60
M18 Embedded Assembly:
  text ".Layer_Name" at 577,-858.49 h60
M19 Embedded Keepout:
  text ".Layer_Name" at 577,-858.49 h60

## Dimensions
0,-400 to 1000,-400 on M2 Board Dimensions
0,0 to 2756,-206 on M2 Board Dimensions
